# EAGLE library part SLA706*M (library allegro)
UNIPOLAR STEPPER-MOTOR TRANSLATOR/DRIVERS Output current: SLA7060M 1.0 A, SLA7061M 2.0 A, SLA7062M 3.0 A Source: 97060.pdf
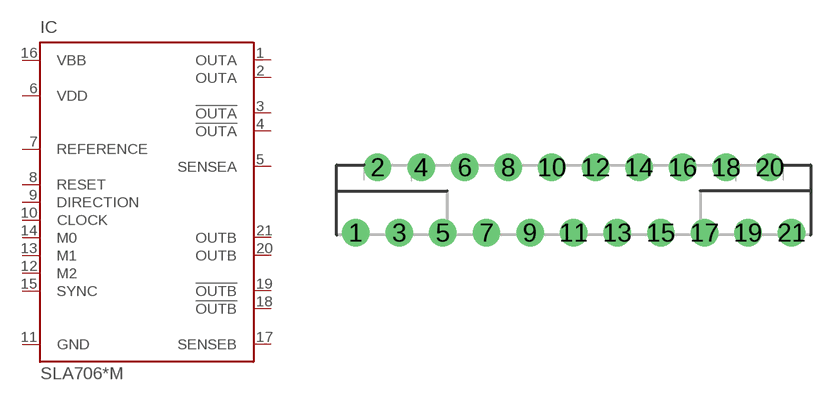
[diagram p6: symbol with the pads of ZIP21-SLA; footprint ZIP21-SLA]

Designator prefix IC

## SLA7060M (MF: ALLEGRO MICROSYSTEMS, INC.; MPN: SLA7060M; OC_FARNELL: unknown; OC_NEWARK: 61H9897), SLA7061M (MF: ALLEGRO MICROSYSTEMS, INC.; MPN: SLA7061M; OC_FARNELL: unknown; OC_NEWARK: 61H9898), SLA7062M (MPN: SLA7062M; OC_FARNELL: 1329628; OC_NEWARK: 77M9253)  [ZIP21-SLA]
1  OUTA  out
2  OUTA  pas
3  !OUTA  out
4  !OUTA  pas
5  SENSEA  in
6  VDD  pwr
7  REFERENCE  in
8  RESET  in
9  DIRECTION  in
10  CLOCK  in
11  GND  pwr
12  M2  in
13  M1  in
14  M0  in
15  SYNC  in
16  VBB  pwr
17  SENSEB  in
18  !OUTB  pas
19  !OUTB  out
20  OUTB  pas
21  OUTB  out

## Footprint ZIP21-SLA (pad centres in mm)
ZIP 21 / SLA706xMLF2102 Source: 97060.pdf
drill 0.9 pad 1.8 round: 1 -14.3,-2.145; 2 -12.87,2.145; 3 -11.44,-2.145; 4 -10.01,2.145; 5 -8.58,-2.145; 6 -7.15,2.145; 7 -5.72,-2.145; 8 -4.29,2.145; 9 -2.86,-2.145; 10 -1.43,2.145; 11 0,-2.145; 12 1.43,2.145; 13 2.86,-2.145; 14 4.29,2.145; 15 5.72,-2.145; 16 7.15,2.145; 17 8.58,-2.145; 18 10.01,2.145; 19 11.44,-2.145; 20 12.87,2.145; 21 14.3,-2.145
